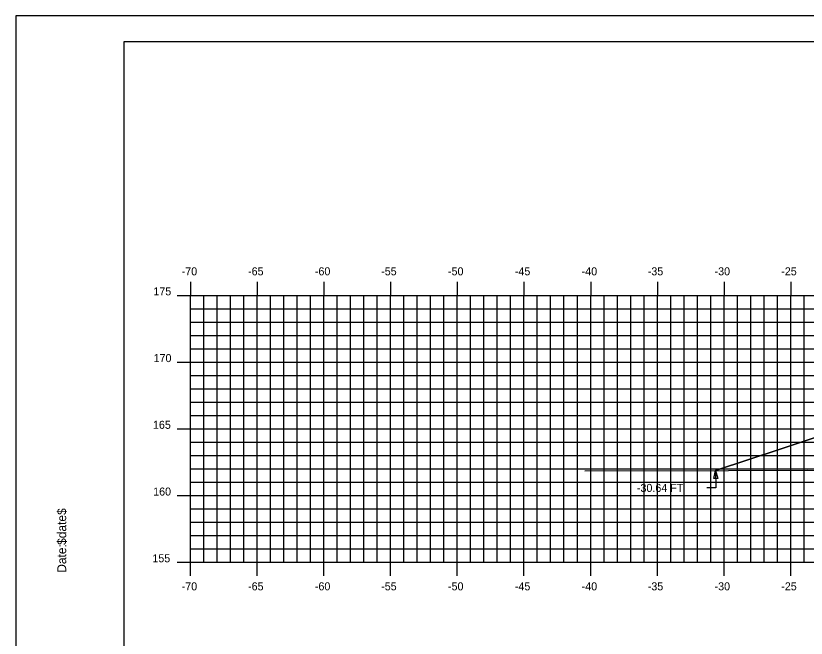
# Model space of a CAD drawing. Extents: x 1140759 to 1140929, y 608981 to 609091.
# Drawn here: x 1140758.9 to 1140818.2, y 609044.6 to 609091.3 of the extents above; entities that cross this region are included whole.
import ezdxf

# ---------------------------------------------------------------- set-up
doc = ezdxf.new("R2010")
doc.units = 0
for name, color, linetype in [('BORDER', 7, 'Continuous'), ('D_Roadway_SlopeLines', 7, 'Continuous'), ('D_Text_Standard', 7, 'Continuous'), ('H_V ANNOTATION', 7, 'Continuous'), ('MAJOR', 7, 'Continuous'), ('MINOR', 7, 'Continuous'), ('PLOT BOUNDARY', 7, 'Continuous'), ('S_Roadway_Centerline', 7, 'Continuous')]:
    doc.layers.add(name, color=color, linetype=linetype)

msp = doc.modelspace()

# ---------------------------------------------------------------- linework, layer by layer
msp.add_lwpolyline([(1140811.365, 609057.2), (1140816.276, 609058.837), (1140819.276, 609059.837), (1140827, 609062.411), (1140827.001, 609062.412), (1140831.001, 609062.572), (1140842.001, 609062.792), (1140853.001, 609062.572), (1140866.241, 609062.042), (1140873.375, 609059.664), (1140876.375, 609058.664), (1140877.252, 609058.372)])
at = {"layer": 'BORDER'}
msp.add_lwpolyline([(1140767.001, 608984.335), (1140927.001, 608984.335), (1140927.001, 609089.335), (1140767.001, 609089.335)], close=True, dxfattribs=at)
at = {"layer": 'D_Roadway_SlopeLines'}
for points in [[(1140819.276, 609059.837), (1140816.276, 609058.837)], [(1140816.276, 609058.837), (1140811.365, 609057.2)]]:
    msp.add_lwpolyline(points, dxfattribs=at)
at = {"layer": 'D_Text_Standard'}
msp.add_lwpolyline([(1140811.365, 609057.2), (1140811.388, 609055.906), (1140810.708, 609055.906)], dxfattribs=at)
msp.add_lwpolyline([(1140811.365, 609057.2), (1140811.521, 609056.62), (1140811.23, 609056.615)], close=True, dxfattribs=at)
at = {"layer": 'MAJOR'}
for p, q in [((1140772.001, 609071.337), (1140772.001, 609070.335)), ((1140777.001, 609071.337), (1140777.001, 609070.335)), ((1140782.001, 609071.337), (1140782.001, 609070.335)), ((1140787.001, 609071.337), (1140787.001, 609070.335)), ((1140792.001, 609071.337), (1140792.001, 609070.335)), ((1140797.001, 609071.337), (1140797.001, 609070.335)), ((1140802.001, 609071.337), (1140802.001, 609070.335)), ((1140807.001, 609071.337), (1140807.001, 609070.335)), ((1140812.001, 609071.337), (1140812.001, 609070.335)), ((1140817.001, 609071.337), (1140817.001, 609070.335)), ((1140770.999, 609070.335), (1140772.001, 609070.335)), ((1140772.001, 609070.335), (1140912.001, 609070.335)), ((1140772.001, 609050.335), (1140772.001, 609070.335)), ((1140772.001, 609050.335), (1140772.001, 609070.335)), ((1140772.001, 609070.335), (1140912.001, 609070.335)), ((1140777.001, 609050.335), (1140777.001, 609070.335)), ((1140782.001, 609050.335), (1140782.001, 609070.335)), ((1140787.001, 609050.335), (1140787.001, 609070.335)), ((1140792.001, 609050.335), (1140792.001, 609070.335)), ((1140797.001, 609050.335), (1140797.001, 609070.335)), ((1140802.001, 609050.335), (1140802.001, 609070.335)), ((1140807.001, 609050.335), (1140807.001, 609070.335)), ((1140812.001, 609050.335), (1140812.001, 609070.335)), ((1140817.001, 609050.335), (1140817.001, 609070.335)), ((1140770.999, 609065.335), (1140772.001, 609065.335)), ((1140772.001, 609065.335), (1140912.001, 609065.335)), ((1140770.999, 609060.335), (1140772.001, 609060.335)), ((1140772.001, 609060.335), (1140912.001, 609060.335)), ((1140770.999, 609055.335), (1140772.001, 609055.335)), ((1140772.001, 609055.335), (1140912.001, 609055.335)), ((1140770.999, 609050.335), (1140772.001, 609050.335)), ((1140772.001, 609050.335), (1140912.001, 609050.335)), ((1140772.001, 609050.335), (1140912.001, 609050.335)), ((1140772.001, 609049.333), (1140772.001, 609050.335)), ((1140777.001, 609049.333), (1140777.001, 609050.335)), ((1140782.001, 609049.333), (1140782.001, 609050.335)), ((1140787.001, 609049.333), (1140787.001, 609050.335)), ((1140792.001, 609049.333), (1140792.001, 609050.335)), ((1140797.001, 609049.333), (1140797.001, 609050.335)), ((1140802.001, 609049.333), (1140802.001, 609050.335)), ((1140807.001, 609049.333), (1140807.001, 609050.335)), ((1140812.001, 609049.333), (1140812.001, 609050.335)), ((1140817.001, 609049.333), (1140817.001, 609050.335))]:
    msp.add_line(p, q, dxfattribs=at)
at = {"layer": 'MINOR'}
for p, q in [((1140773.001, 609050.335), (1140773.001, 609070.335)), ((1140774.001, 609050.335), (1140774.001, 609070.335)), ((1140775.001, 609050.335), (1140775.001, 609070.335)), ((1140776.001, 609050.335), (1140776.001, 609070.335)), ((1140778.001, 609050.335), (1140778.001, 609070.335)), ((1140779.001, 609050.335), (1140779.001, 609070.335)), ((1140780.001, 609050.335), (1140780.001, 609070.335)), ((1140781.001, 609050.335), (1140781.001, 609070.335)), ((1140783.001, 609050.335), (1140783.001, 609070.335)), ((1140784.001, 609050.335), (1140784.001, 609070.335)), ((1140785.001, 609050.335), (1140785.001, 609070.335)), ((1140786.001, 609050.335), (1140786.001, 609070.335)), ((1140788.001, 609050.335), (1140788.001, 609070.335)), ((1140789.001, 609050.335), (1140789.001, 609070.335)), ((1140790.001, 609050.335), (1140790.001, 609070.335)), ((1140791.001, 609050.335), (1140791.001, 609070.335)), ((1140793.001, 609050.335), (1140793.001, 609070.335)), ((1140794.001, 609050.335), (1140794.001, 609070.335)), ((1140795.001, 609050.335), (1140795.001, 609070.335)), ((1140796.001, 609050.335), (1140796.001, 609070.335)), ((1140798.001, 609050.335), (1140798.001, 609070.335)), ((1140799.001, 609050.335), (1140799.001, 609070.335)), ((1140800.001, 609050.335), (1140800.001, 609070.335)), ((1140801.001, 609050.335), (1140801.001, 609070.335)), ((1140803.001, 609050.335), (1140803.001, 609070.335)), ((1140804.001, 609050.335), (1140804.001, 609070.335)), ((1140805.001, 609050.335), (1140805.001, 609070.335)), ((1140806.001, 609050.335), (1140806.001, 609070.335)), ((1140808.001, 609050.335), (1140808.001, 609070.335)), ((1140809.001, 609050.335), (1140809.001, 609070.335)), ((1140810.001, 609050.335), (1140810.001, 609070.335)), ((1140811.001, 609050.335), (1140811.001, 609070.335)), ((1140813.001, 609050.335), (1140813.001, 609070.335)), ((1140814.001, 609050.335), (1140814.001, 609070.335)), ((1140815.001, 609050.335), (1140815.001, 609070.335)), ((1140816.001, 609050.335), (1140816.001, 609070.335)), ((1140818.001, 609050.335), (1140818.001, 609070.335)), ((1140772.001, 609069.335), (1140912.001, 609069.335)), ((1140772.001, 609069.335), (1140773.003, 609069.335)), ((1140772.001, 609068.335), (1140912.001, 609068.335)), ((1140772.001, 609068.335), (1140773.003, 609068.335)), ((1140772.001, 609067.335), (1140912.001, 609067.335)), ((1140772.001, 609067.335), (1140773.003, 609067.335)), ((1140772.001, 609066.335), (1140912.001, 609066.335)), ((1140772.001, 609066.335), (1140773.003, 609066.335)), ((1140772.001, 609064.335), (1140912.001, 609064.335)), ((1140772.001, 609064.335), (1140773.003, 609064.335)), ((1140772.001, 609063.335), (1140912.001, 609063.335)), ((1140772.001, 609063.335), (1140773.003, 609063.335)), ((1140772.001, 609062.335), (1140912.001, 609062.335)), ((1140772.001, 609062.335), (1140773.003, 609062.335)), ((1140772.001, 609061.335), (1140912.001, 609061.335)), ((1140772.001, 609061.335), (1140773.003, 609061.335)), ((1140772.001, 609059.335), (1140912.001, 609059.335)), ((1140772.001, 609059.335), (1140773.003, 609059.335)), ((1140772.001, 609058.335), (1140912.001, 609058.335)), ((1140772.001, 609058.335), (1140773.003, 609058.335)), ((1140772.001, 609057.335), (1140912.001, 609057.335)), ((1140772.001, 609057.335), (1140773.003, 609057.335)), ((1140772.001, 609056.335), (1140912.001, 609056.335)), ((1140772.001, 609056.335), (1140773.003, 609056.335)), ((1140772.001, 609054.335), (1140912.001, 609054.335)), ((1140772.001, 609054.335), (1140773.003, 609054.335)), ((1140772.001, 609053.335), (1140912.001, 609053.335)), ((1140772.001, 609053.335), (1140773.003, 609053.335)), ((1140772.001, 609052.335), (1140912.001, 609052.335)), ((1140772.001, 609052.335), (1140773.003, 609052.335)), ((1140772.001, 609051.335), (1140912.001, 609051.335)), ((1140772.001, 609051.335), (1140773.003, 609051.335))]:
    msp.add_line(p, q, dxfattribs=at)
at = {"layer": 'PLOT BOUNDARY'}
msp.add_lwpolyline([(1140758.908, 608981.276), (1140928.908, 608981.276), (1140928.908, 609091.276), (1140758.908, 609091.276)], close=True, dxfattribs=at)
at = {"layer": 'S_Roadway_Centerline'}
msp.add_lwpolyline([(1140801.566, 609057.193), (1140812.339, 609057.2), (1140818.229, 609057.238), (1140821.395, 609057.189), (1140823.921, 609056.785), (1140825.618, 609057.158), (1140827.397, 609057.494), (1140828.704, 609057.63), (1140830.196, 609057.796), (1140835.206, 609057.946), (1140841.168, 609058.151), (1140846.371, 609057.971), (1140852.246, 609057.857), (1140853.573, 609057.771), (1140855.293, 609057.642), (1140857.407, 609057.124), (1140859.515, 609056.755), (1140863.547, 609056.636), (1140867.204, 609058.18), (1140881.91, 609058.461), (1140889.197, 609058.77)], dxfattribs=at)

# ---------------------------------------------------------------- texts
at = {"layer": 'BORDER'}
for s, p in [('$date$', (1140762.686, 609051.64)), ('Date:', (1140762.686, 609049.552))]:
    msp.add_text(s, height=0.6696, rotation=90, dxfattribs=at).set_placement(p)
at = {"layer": 'D_Text_Standard'}
msp.add_text('-30.64 FT', height=0.6, dxfattribs=at).set_placement((1140805.468, 609055.606))
at = {"layer": 'H_V ANNOTATION'}
for s, p in [('-70', (1140771.343, 609071.835)), ('-65', (1140776.319, 609071.835)), ('-60', (1140781.327, 609071.835)), ('-50', (1140791.305, 609071.835)), ('-40', (1140801.327, 609071.835)), ('-35', (1140806.281, 609071.835)), ('-30', (1140811.289, 609071.835)), ('-25', (1140816.287, 609071.835)), ('-55', (1140786.297, 609071.835)), ('-45', (1140796.319, 609071.835)), ('175', (1140769.222, 609070.335)), ('170', (1140769.238, 609065.335)), ('165', (1140769.19, 609060.335)), ('160', (1140769.206, 609055.335)), ('155', (1140769.147, 609050.335)), ('-70', (1140771.343, 609048.235)), ('-65', (1140776.319, 609048.235)), ('-60', (1140781.327, 609048.235)), ('-55', (1140786.297, 609048.235)), ('-50', (1140791.305, 609048.235)), ('-45', (1140796.319, 609048.235)), ('-40', (1140801.327, 609048.235)), ('-35', (1140806.281, 609048.235)), ('-30', (1140811.289, 609048.235)), ('-25', (1140816.287, 609048.235))]:
    msp.add_text(s, height=0.6, dxfattribs=at).set_placement(p)
at = {"layer": 'MAJOR'}
msp.add_text('-', height=0.006, dxfattribs=at).set_placement((1140771.997, 609050.335))

doc.saveas('drawing.dxf')
